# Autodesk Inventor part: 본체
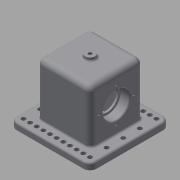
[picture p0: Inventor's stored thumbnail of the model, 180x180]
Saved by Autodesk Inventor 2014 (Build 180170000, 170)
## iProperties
Created: 2018-11
Part Number: 본체
Material: Generic
Document SubType Name: Modeling
Designer: kh
Density: 1 g/cm^3
Appearance: Default
Author: kh
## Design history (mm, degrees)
sketch "스케치1"
  geometry: L1 (-60, -60)-(60, -60); L2 (60, -60)-(60, 60); L3 (60, 60)-(-60, 60); L4 (-60, 60)-(-60, -60); L5 (-60, -60)-(60, 60); L6 (60, -60)-(-60, 60); 1 further point
  constraints: 12 end point, 2 midpoint, 2 parallel, 1 horizontal, 1 perpendicular
  dimensions: "d0" = 120 distance of L2.end L3.end; "d1" = 120 distance of L1.end L2.end
extrude "돌출1" new body sketch "스케치1" distance "d2" = 10; taper "d3" = 0 deg
sketch "스케치2"
  geometry: L1 (-40, -40)-(40, -40); L2 (40, -40)-(40, 40); L3 (40, 40)-(-40, 40); L4 (-40, 40)-(-40, -40); L5 (-40, -40)-(40, 40); L6 (40, -40)-(-40, 40); 1 further point
  constraints: 12 end point, 2 midpoint, 2 parallel, 1 horizontal, 1 perpendicular
  dimensions: "d4" = 80 distance of L2.end L3.end; "d5" = 80 distance of L1.end L2.end
extrude "돌출2" join sketch "스케치2" distance "d6" = 80; taper "d7" = 0 deg
sketch "스케치3"
  geometry: C1 r 7.5 at (0, 0); 1 further point
  constraints: 1 centre point, 1 coincident
  dimensions: "d8" = 15 diameter of C1
extrude "돌출3" join sketch "스케치3" distance "d9" = 5; taper "d10" = 0 deg
sketch "스케치4"
  geometry: L1 (40, 10)-(-40, 10) reference; L2 (40, 10)-(40, 90) reference; L3 (-40, 90)-(40, 90) reference; L4 (-40, 10)-(-40, 90) reference; L5 (-60, 0)-(60, 0) reference; L6 (60, 0)-(60, 10) reference; L7 (-60, 10)-(60, 10) reference; L8 (-60, 0)-(-60, 10) reference; L9 (7.5, 95)-(-7.5, 95) reference; L10 (-7.5, 90)-(7.5, 90) reference; L11 (0, 0)-(0, 48); L12 (0, 48)-(-40, 48); L13 (0, 48)-(40, 48); L14 (40, 48)-(26, 48); L15 (26, 48)-(26, 68); L16 (26, 68)-(40, 68); L17 (40, 68)-(40, 48); L18 (-40, 48)-(-26, 48); L19 (-26, 48)-(-26, 68); L20 (-26, 68)-(-40, 68); L21 (-40, 68)-(-40, 48); L22 (26, 48)-(-26, 48); L23 (-26, 48)-(-26, 64.5); L24 (26, 64.5)-(26, 48); L25 (26, 48)-(23, 48); L26 (23, 48)-(23, 64.5); L27 (23, 64.5)-(26, 64.5); L28 (26, 64.5)-(26, 48); L29 (-26, 48)-(-23, 48); L30 (-23, 48)-(-23, 64.5); L31 (-23, 64.5)-(-26, 64.5); L32 (-26, 64.5)-(-26, 48)
  constraints: 44 end point, 10 equal length, 7 perpendicular, 5 horizontal, 3 point on line
  dimensions: "d11" = 48 distance of L11.start L11.end; "d12" = 40 diameter of L16 L13; "d14" = 40 diameter of L20 L12; "d15" = 14 distance of L15.end L16.end; "d16" = 14 distance of L19.end L20.end; "d17" = 3 distance of L26.end L27.end; "d18" = 3 distance of L30.end L31.end; "d19" = 33 diameter of L31 L22; "d20" = 33 diameter of L27 L13
revolve "회전1" sketch "스케치4" stored, may be unused: angle "d21" = 90 deg
sketch "스케치5"
  geometry: L1 (-23, -30)-(23, -30); L2 (23, -30)-(23, 30); L3 (23, 30)-(-23, 30); L4 (-23, 30)-(-23, -30); L5 (-23, -30)-(23, 30); L6 (23, -30)-(-23, 30); 1 further point
  constraints: 12 end point, 2 midpoint, 2 parallel, 1 horizontal, 1 perpendicular
  dimensions: "d22" = 46 distance of L2.end L3.end; "d23" = 60 distance of L1.end L2.end
extrude "돌출4" cut sketch "스케치5" distance "d24" = 80; taper "d25" = 0 deg
sketch "스케치6" dims "d26" = 52
  geometry: L1 (0, 0)-(0, 80) reference; L2 (0, 0)-(80, 0) reference; L3 (80, 80)-(80, 0) reference; L4 (0, 80)-(80, 80) reference; L5 (38, 40)-(64, 40); C1 r 20 at (38, 40) reference; 2 further points
  constraints: 2 coincident, 2 end point, 1 horizontal alignment, 1 parallel, 2 other
hole "구멍1" sketch "스케치6" at (64, 40) diameter "d27" = 3.242; stored, may be unused: countersink angle "d31" = 90 deg, drill point angle "d33" = 118 deg; dims "d28" = 8, "d29" = 4, "d30" = 2, "d32" = 10
sketch "스케치7" dims "d34" = 52
  geometry: L1 (0, 80)-(0, 0) reference; L2 (0, 80)-(-80, 80) reference; L3 (-80, 0)-(-80, 80) reference; L4 (0, 0)-(-80, 0) reference; L5 (-38, 40)-(-64, 40); C1 r 20 at (-38, 40) reference; 2 further points
  constraints: 2 coincident, 2 end point, 1 horizontal alignment, 1 parallel, 2 other
hole "구멍2" sketch "스케치7" at (-64, 40) diameter "d35" = 3.242; stored, may be unused: countersink angle "d39" = 90 deg, drill point angle "d41" = 118 deg; dims "d36" = 8, "d37" = 4, "d38" = 2, "d40" = 10
sketch "스케치9"
  geometry: L1 (-50, -50)-(50, -50); L2 (50, -50)-(50, 50); L3 (50, 50)-(-50, 50); L4 (-50, 50)-(-50, -50); L5 (-50, -50)-(50, 50); L6 (50, -50)-(-50, 50); 3 further points
  constraints: 12 end point, 2 coincident, 2 midpoint, 2 parallel, 1 horizontal, 1 perpendicular
  dimensions: "d48" = 100 distance of L2.end L3.end; "d49" = 100 distance of L3.end L1.start
hole "구멍3" sketch "스케치9" at (-50, 50), (-50, -50) diameter "d50" = 6.6; stored, may be unused: countersink angle "d54" = 90 deg, drill point angle "d56" = 118 deg; dims "d51" = 6.6, "d52" = 4, "d53" = 2, "d55" = 10
sketch "스케치10"
  geometry: L1 (-50, -25)-(50, -25); L2 (50, -25)-(50, 25); L3 (50, 25)-(-50, 25); L4 (-50, 25)-(-50, -25); L5 (-50, -25)-(50, 25); L6 (50, -25)-(-50, 25); 7 further points
  constraints: 12 end point, 4 coincident, 4 midpoint, 2 parallel, 1 horizontal, 1 perpendicular
  dimensions: "d60" = 50 distance of L3.end L1.start; "d61" = 100 distance of L2.end L3.end
hole "구멍4" sketch "스케치10" at (-50, 25), (-50, 0), (-50, -25), (50, 25), (50, 0), (50, -25) diameter "d62" = 6.6; stored, may be unused: countersink angle "d66" = 90 deg, drill point angle "d68" = 118 deg; dims "d63" = 6.6, "d64" = 4, "d65" = 2, "d67" = 10
fillet "모깎기1" dims "d69" = 10, "d70" = 8
fillet "모깎기2" dims "d71" = 8, "d72" = 3
hole "구멍5" diameter "d75" = 4.917; stored, may be unused: countersink angle "d79" = 90 deg, drill point angle "d81" = 118 deg; dims "d73" = 10, "d74" = 10, "d76" = 6.6, "d77" = 4, "d78" = 2, "d80" = 10
fillet "모깎기3" dims "d82" = 0.6
chamfer "모따기1" distance "d83" = 1; stored, may be unused: second distance "d84" = 2, angle "d85" = 45 deg
fillet "모깎기4" dims "d86" = 3
fillet "모깎기5" dims "d87" = 3
sketch "스케치11"
  geometry: L1 (32, 13)-(32, -35); L2 (56.903, -38.385)-(7.129, -38.385); L3 (7.129, -38.385)-(7.129, -31.18); L4 (7.129, -31.18)-(56.903, -31.18); L5 (56.903, -31.18)-(56.903, -38.385)
  constraints: 2 end point, 1 vertical, 2 other
  dimensions: "d88" = 48 distance of L1.start L1.end
feature "엠보싱2" sketch "스케치11" dims "d0" = 120, "d1" = 120, "d89" = 0.5, "d90" = 0
node "솔리드1"
pattern_circular "원형 패턴1" dims angle "d43" = 360 deg
pattern_linear "직사각형 패턴1" dims "d59" = 10
node "투영된 루프1"
node "투영된 루프2"
node "투영된 루프3"
node "투영된 루프4"
node "투영된 루프5"
